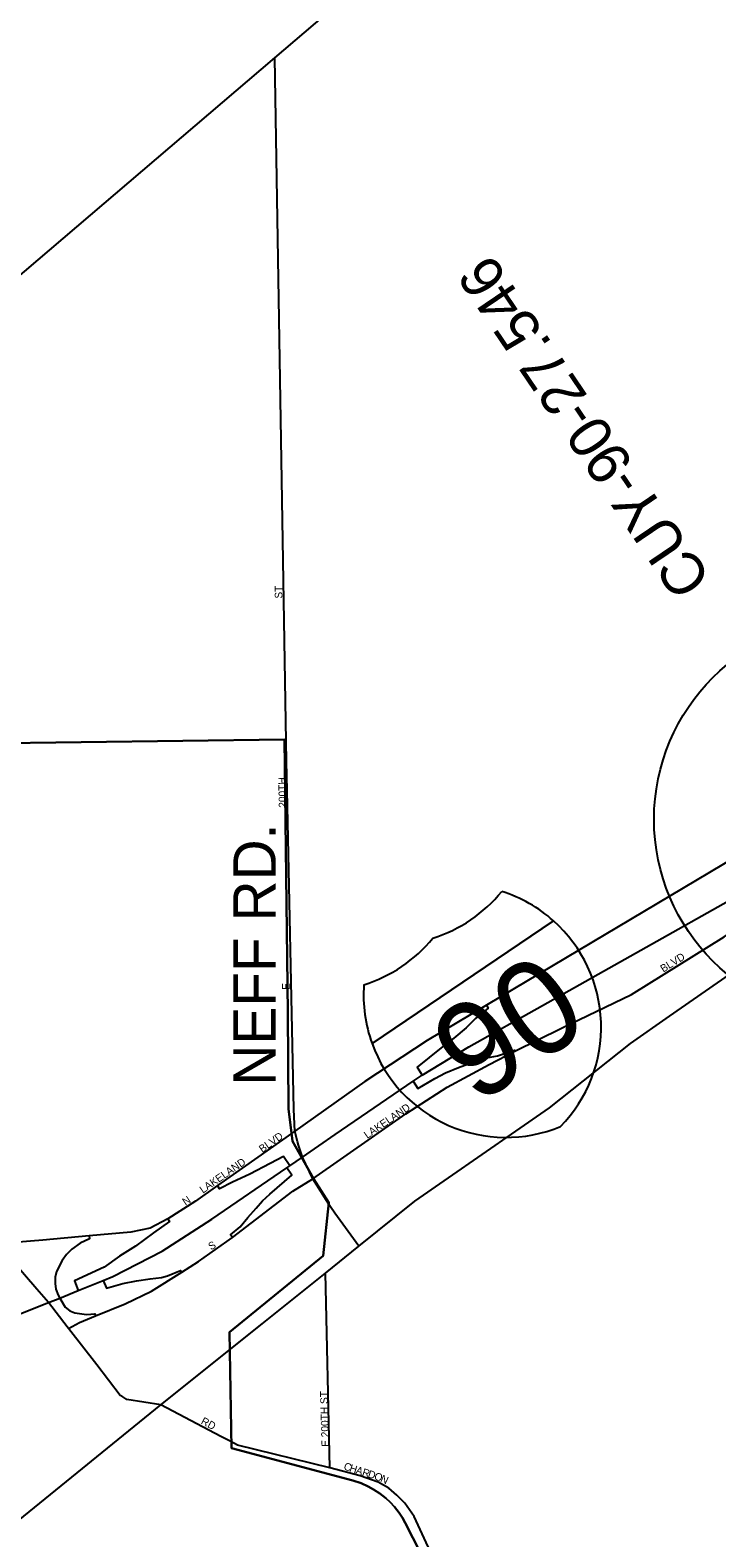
# Model space of a CAD drawing. Extents: x 2139079 to 2262683, y 1235796 to 1334992.
# Drawn here: x 2229551 to 2234072, y 1303635 to 1313569 of the extents above; entities that cross this region are included whole.
import ezdxf

# ---------------------------------------------------------------- set-up
doc = ezdxf.new("R2010")
doc.units = 0
for name, color, linetype in [('Default', 7, 'Continuous'), ('GM_X_City_Street', 7, 'Continuous'), ('GM_X_City_Street_Text', 7, 'Continuous'), ('GM_X_Interchange_Ramps', 7, 'Continuous'), ('GM_X_Interstate_Route', 7, 'Continuous'), ('GM_X_Interstate_Shield', 7, 'Continuous'), ('GM_X_State_Route', 7, 'Continuous'), ('SH_Text', 7, 'Continuous')]:
    doc.layers.add(name, color=color, linetype=linetype)

msp = doc.modelspace()

# ---------------------------------------------------------------- linework, layer by layer
at = {"layer": 'GM_X_City_Street'}
for points in [[(2231239.1, 1308749.6), (2231161.4, 1313386.3)], [(2231284, 1306564.7), (2231242.3, 1308559.2), (2231239.1, 1308749.6)], [(2234864.8, 1308534.7), (2234767.1, 1308474.3), (2234196.4, 1308121.7), (2232556.2, 1307144.9), (2232165.3, 1306912.5), (2231754.3, 1306641.5), (2231294.5, 1306314.6)], [(2231411.7, 1306001.3), (2232025.1, 1306428.8), (2232297.3, 1306605.4), (2232572.8, 1306754.5), (2232742.6, 1306841.7), (2233049.3, 1306992.5), (2233509.7, 1307216.3), (2234119.4, 1307595.6), (2234373.7, 1307775.1), (2234835.3, 1308089.6), (2234925.7, 1308146.3)], [(2231077.9, 1305045.6), (2231494.7, 1305378.6), (2231714.2, 1305557.8), (2232082.5, 1305853.7), (2232970.1, 1306469.4), (2233502.9, 1306892.5), (2233761.1, 1307073.7), (2234472, 1307566.7), (2234674.5, 1307698.4), (2234734.5, 1307712.9), (2234818.9, 1307719.4), (2234933.9, 1307718)], [(2231310.7, 1306247), (2231294.5, 1306314.6), (2231286.2, 1306458.5), (2231284, 1306564.7)], [(2231294.5, 1306314.6), (2230784.6, 1305955.9), (2230638.5, 1305853.4), (2230457.2, 1305736.7), (2230340.9, 1305675.6), (2230212.8, 1305648.7), (2229939.3, 1305624.3), (2229634.8, 1305597.1), (2229335.6, 1305573.3), (2229331.3, 1305572)], [(2231325.3, 1306195.9), (2231316.7, 1306221.9), (2231310.7, 1306247)], [(2231556.6, 1305775.3), (2231527.4, 1305815.6), (2231411.7, 1306001.3), (2231342.9, 1306143), (2231325.3, 1306195.9)], [(2229803.5, 1305014.2), (2229875.8, 1305053.5), (2229982, 1305097.6), (2230176.4, 1305178.1), (2230350.3, 1305261.2), (2230548.4, 1305386.9), (2230658.5, 1305456.8), (2230883.4, 1305614.8), (2231280.8, 1305918.8), (2231411.7, 1306001.3)], [(2231714.2, 1305557.8), (2231556.6, 1305775.3)], [(2229594.4, 1305274.8), (2229335.6, 1305573.3), (2229317.2, 1305596.4)], [(2231524.1, 1304095.9), (2231494.7, 1305378.6)], [(2229793.9, 1305026.7), (2229671.9, 1305185.4), (2229594.4, 1305274.8)], [(2229193.8, 1303478.3), (2229473.2, 1303749.8), (2230411, 1304512.8), (2231077.9, 1305045.6)], [(2229988.7, 1304774.7), (2229803.5, 1305014.2), (2229793.9, 1305026.7)], [(2230153.8, 1304567.9), (2230144.3, 1304573.5), (2229988.7, 1304774.7)], [(2230871.3, 1304269.6), (2230807, 1304303.6), (2230411, 1304512.8), (2230187.4, 1304547.9), (2230153.8, 1304567.9)], [(2233088.2, 1301840), (2233073.5, 1301864.9), (2233067.4, 1301875.3), (2232171, 1303576.2), (2232079.2, 1303776.5), (2232018.5, 1303862.8), (2231965.8, 1303917.1), (2231913.1, 1303961.8), (2231842.8, 1304001.7), (2231723.7, 1304043.3), (2231524.1, 1304095.9), (2230915.6, 1304246.1), (2230871.3, 1304269.6)]]:
    msp.add_lwpolyline(points, dxfattribs=at)
at = {"layer": 'GM_X_Interchange_Ramps'}
for points in [[(2232556.2, 1307144.9), (2232567.5, 1307124.6), (2232482.1, 1307057.3), (2232421.2, 1306996.4), (2232341.3, 1306928.5), (2232257.3, 1306864.3), (2232099.7, 1306737.3), (2232131.2, 1306684.7)], [(2232072.2, 1306644.2), (2232104.4, 1306595.7), (2232214.8, 1306661.6), (2232284.6, 1306698.8), (2232371.3, 1306734.2), (2232477.9, 1306774.3), (2232555.4, 1306798.1), (2232628.5, 1306812.2), (2232739.2, 1306848.5), (2232742.6, 1306841.7)], [(2231261.1, 1306087), (2231218.5, 1306148.1), (2231130.6, 1306101.5), (2230997.1, 1306032.3), (2230882.3, 1305978.2), (2230798.3, 1305935.7), (2230784.6, 1305955.9)], [(2230883.4, 1305614.8), (2230870.9, 1305632.1), (2230933.8, 1305683.8), (2230983.4, 1305745.8), (2231038.7, 1305807.2), (2231080.1, 1305855.3), (2231128, 1305900.4), (2231272.9, 1306025.3), (2231240, 1306072.6)], [(2230457.2, 1305736.7), (2230468.8, 1305719.5), (2230362, 1305644.1), (2230243.7, 1305556.2), (2230138.1, 1305492.1), (2230038.4, 1305419.3), (2229842.5, 1305329.2), (2229867.2, 1305264.9)], [(2229939.3, 1305624.3), (2229941.6, 1305605.6), (2229880.4, 1305577.1), (2229825.3, 1305536.8), (2229789, 1305501.8), (2229760.8, 1305462.2), (2229724.7, 1305389.4), (2229715.2, 1305353), (2229715.3, 1305311.5), (2229720.5, 1305273.4), (2229734.3, 1305234), (2229745.3, 1305215.3), (2229781.3, 1305154.4), (2229812.6, 1305131.6), (2229844.6, 1305117.9), (2229922.7, 1305108), (2229949.1, 1305108.1), (2229976, 1305111.7), (2229982, 1305097.6)], [(2230031.5, 1305331.8), (2230052.5, 1305281.3), (2230160.3, 1305311.1), (2230250.9, 1305329), (2230340.9, 1305341.3), (2230415.8, 1305350.6), (2230454.6, 1305362.5), (2230541.3, 1305397.9), (2230548.4, 1305386.9)]]:
    msp.add_lwpolyline(points, dxfattribs=at)
at = {"layer": 'GM_X_Interstate_Route'}
for points in [[(2232273.7, 1303236.4), (2232020.4, 1303733.6), (2232001.7, 1303766.9), (2231979.4, 1303800.9), (2231949.3, 1303839.4), (2231920.2, 1303870.9), (2231893.4, 1303896), (2231853.9, 1303927.5), (2231812.2, 1303954.9), (2231775.9, 1303974.7), (2231730.2, 1303994.9), (2231675.3, 1304013), (2230877.2, 1304226.9), (2230862.2, 1304989.9), (2231480.3, 1305492.8), (2231516.4, 1305844.9), (2231416.1, 1306002.7), (2231277, 1306249.4), (2231251.8, 1306461.1), (2231246.8, 1307095.9), (2231225.8, 1308895.9), (2228546, 1308860.7)], [(2228546, 1308860.7), (2231225.8, 1308895.9), (2231246.8, 1307095.9), (2231251.8, 1306461.1), (2231277, 1306249.4), (2231416.1, 1306002.7), (2231516.4, 1305844.9), (2231480.3, 1305492.8), (2230862.2, 1304989.9), (2230877.2, 1304226.9), (2231675.3, 1304013), (2231730.2, 1303994.9), (2231775.9, 1303974.7), (2231812.2, 1303954.9), (2231853.9, 1303927.5), (2231893.4, 1303896), (2231920.2, 1303870.9), (2231949.3, 1303839.4), (2231979.4, 1303800.9), (2232001.7, 1303766.9), (2232020.4, 1303733.6), (2232273.7, 1303236.4)], [(2232273.7, 1303236.4), (2232020.4, 1303733.6), (2232001.7, 1303766.9), (2231979.4, 1303800.9), (2231949.3, 1303839.4), (2231920.2, 1303870.9), (2231893.4, 1303896), (2231853.9, 1303927.5), (2231812.2, 1303954.9), (2231775.9, 1303974.7), (2231730.2, 1303994.9), (2231675.3, 1304013), (2230877.2, 1304226.9), (2230862.2, 1304989.9), (2231480.3, 1305492.8), (2231516.4, 1305844.9), (2231416.1, 1306002.7), (2231277, 1306249.4), (2231251.8, 1306461.1), (2231246.8, 1307095.9), (2231225.8, 1308895.9), (2228546, 1308860.7)], [(2231560, 1306292.2), (2232072.2, 1306644.2), (2232131.2, 1306684.7), (2232438.4, 1306869.9), (2232923.5, 1307142), (2234219.6, 1307872.3)], [(2228943.7, 1304896), (2229671.9, 1305185.4), (2229745.3, 1305215.3), (2229867.2, 1305264.9), (2230031.5, 1305331.8), (2230095.2, 1305357.8), (2230418.9, 1305524.9), (2230747.8, 1305735.6), (2231240, 1306072.6), (2231261.1, 1306087), (2231342.9, 1306143), (2231560, 1306292.2)]]:
    msp.add_lwpolyline(points, dxfattribs=at)
at = {"layer": 'GM_X_Interstate_Shield'}
for p, q in [((2231801.8, 1306891.7), (2232996.4, 1307700.9)), ((2232996.4, 1307700.9), (2231801.8, 1306891.7)), ((2232996.4, 1307700.9), (2231801.8, 1306891.7))]:
    msp.add_line(p, q, dxfattribs=at)
for centre, start, end in [((2231926, 1308483.3), 287.12046, 321.10231), ((2232372.8, 1307000.8), 48.30474, 72.44243), ((2232372.8, 1307000.8), 315.64835, 48.30474), ((2231472.3, 1308176.1), 287.12046, 321.10231), ((2232683.3, 1307211.1), 175.78035, 199.91803), ((2232683.3, 1307211.1), 199.91803, 292.57443)]:
    msp.add_arc(centre, 937.5, start, end, dxfattribs=at)
at = {"layer": 'GM_X_State_Route'}
msp.add_lwpolyline([(2228551.1, 1311159.1), (2231161.4, 1313386.3), (2233896.5, 1315721.3)], dxfattribs=at)
at = {"layer": 'SH_Text'}
msp.add_circle((2234979.8, 1308369.8), 1321, dxfattribs=at)

# ---------------------------------------------------------------- texts
at = {"layer": 'Default'}
msp.add_text('CUY-90-27.546', height=279.999, rotation=124.11128, dxfattribs=at).set_placement((2234043.4, 1309950.6))
at = {"layer": 'GM_X_City_Street_Text'}
for s, rotation, p in [('ST', 90, (2231211.5, 1309823.8)), ('200TH', 91.16851, (2231237.9, 1308446.4)), ('BLVD', 32.00476, (2233719.5, 1307359)), ('E', 90, (2231259.9, 1307245.4)), ('LAKELAND', 34.31343, (2231770, 1306263.2)), ('BLVD', 35.35989, (2231079.1, 1306170.7)), ('LAKELAND', 34.60834, (2230687.9, 1305902.6)), ('N', 33.67885, (2230573.3, 1305823.2)), ('S', 29.73143, (2230741, 1305528.8)), ('E 200TH ST', 91.61576, (2231519.5, 1304235.6)), ('RD', 332.0986, (2230670.8, 1304389.2)), ('C', 342.17946, (2231611, 1304086.4)), ('H', 342.17696, (2231648.7, 1304074.3)), ('A', 342.1986, (2231690.6, 1304060.8)), ('R', 342.17946, (2231732.5, 1304047.3)), ('D', 342.15956, (2231770.2, 1304035.2)), ('O', 340.27268, (2231811.6, 1304021.9)), ('N', 335.90879, (2231852.1, 1304007.4))]:
    msp.add_text(s, height=50, rotation=rotation, dxfattribs=at).set_placement(p)
at = {"layer": 'GM_X_Interchange_Ramps'}
msp.add_text('NEFF RD.', height=280, rotation=90, dxfattribs=at).set_placement((2231168.1, 1306614.9))
at = {"layer": 'GM_X_Interstate_Shield'}
msp.add_text('90', height=625, rotation=34.11139, dxfattribs=at).set_placement((2232487.6, 1306478.7))

doc.saveas('drawing.dxf')
